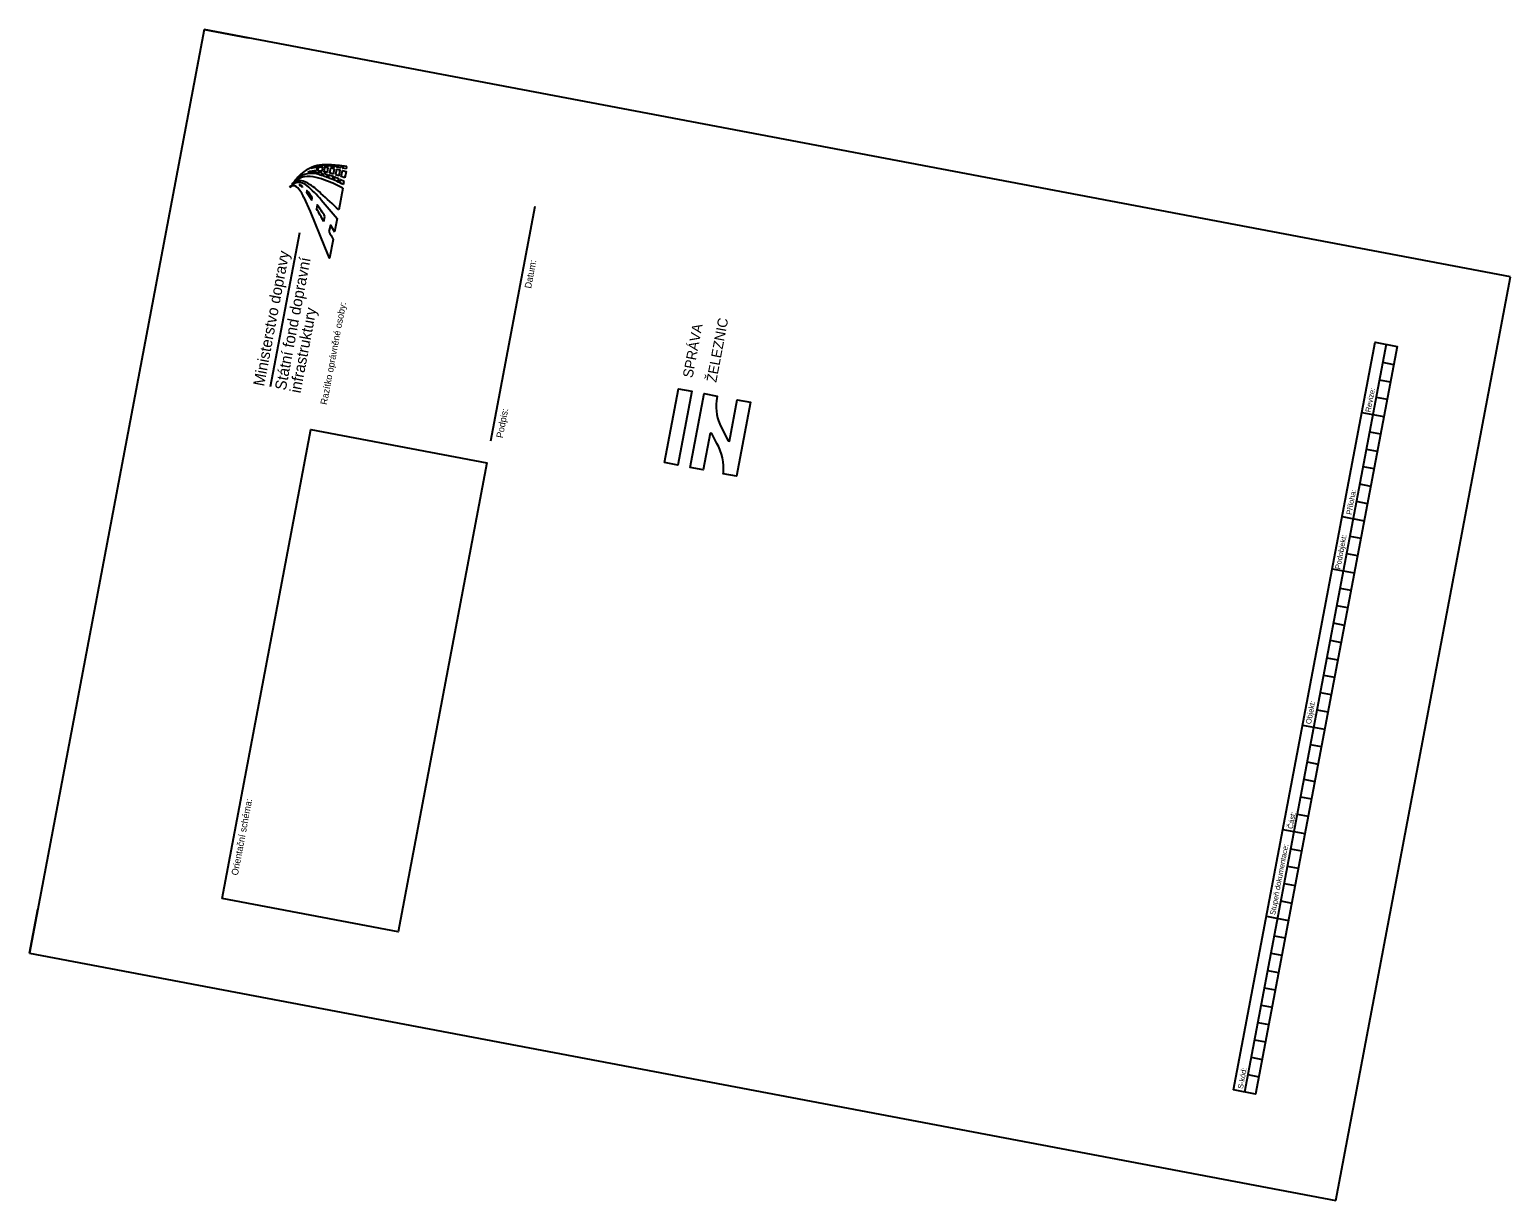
# Model space of a CAD drawing. Extents: x -526979 to -525529, y -1078878 to -1076692.
# Drawn here: x -525859.9 to -525529, y -1076953.6 to -1076692.1 of the extents above; entities that cross this region are included whole.
import ezdxf

# ---------------------------------------------------------------- set-up
doc = ezdxf.new("R2010")
doc.units = 0
for name, color, linetype in [('Default', 7, 'Continuous'), ('ramek', 7, 'Continuous'), ('Rozpiska_Logo', 7, 'Continuous'), ('Rozpiska_pola_3', 7, 'Continuous'), ('Rozpiska_pole_2', 7, 'Continuous'), ('Rozpiska_pole_8', 7, 'Continuous')]:
    doc.layers.add(name, color=color, linetype=linetype)

# ---------------------------------------------------------------- blocks, each defined once
blk = doc.blocks.new('_U77')
at = {"layer": 'Rozpiska_pole_8'}
for p, q in [((85, 0), (-85, 0)), ((-81.05, 0), (-81.05, -2.5)), ((-77.1, 0), (-77.1, -2.5)), ((-73.15, 0), (-73.15, -2.5)), ((-69.2, 0), (-69.2, -2.5)), ((-65.25, 0), (-65.25, -2.5)), ((-61.3, 0), (-61.3, -2.5)), ((-57.35, 0), (-57.35, -2.5)), ((-53.4, 0), (-53.4, -2.5)), ((-49.45, 0), (-49.45, -2.5)), ((-45.5, 2.5), (-45.5, -2.5)), ((-41.55, 0), (-41.55, -2.5)), ((-37.6, 0), (-37.6, -2.5)), ((-33.65, 0), (-33.65, -2.5)), ((-29.7, 0), (-29.7, -2.5)), ((-25.75, 2.5), (-25.75, -2.5)), ((-21.8, 0), (-21.8, -2.5)), ((-17.85, 0), (-17.85, -2.5)), ((-13.9, 0), (-13.9, -2.5)), ((-9.95, 0), (-9.95, -2.5)), ((-6, 0), (-6, -2.5)), ((-2.05, 2.5), (-2.05, -2.5)), ((1.9, 0), (1.9, -2.5)), ((5.85, 0), (5.85, -2.5)), ((9.8, 0), (9.8, -2.5)), ((13.75, 0), (13.75, -2.5)), ((17.7, 0), (17.7, -2.5)), ((21.65, 0), (21.65, -2.5)), ((25.6, 0), (25.6, -2.5)), ((29.55, 0), (29.55, -2.5)), ((33.5, 2.5), (33.5, -2.5)), ((37.45, 0), (37.45, -2.5)), ((41.4, 0), (41.4, -2.5)), ((45.35, 2.5), (45.35, -2.5)), ((49.3, 0), (49.3, -2.5)), ((53.25, 0), (53.25, -2.5)), ((57.2, 0), (57.2, -2.5)), ((61.15, 0), (61.15, -2.5)), ((65.1, 0), (65.1, -2.5)), ((69.05, 2.5), (69.05, -2.5)), ((73, 0), (73, -2.5)), ((76.95, 0), (76.95, -2.5)), ((80.9, 0), (80.9, -2.5))]:
    blk.add_line(p, q, dxfattribs=at)
blk.add_lwpolyline([(-85, 2.5), (85, 2.5), (85, -2.5), (-85, -2.5)], close=True, dxfattribs=at)
at = {"layer": 'Default'}
for s, p in [('S-kód:', (-84.45, 0.49)), ('Stupeň dokumentace:', (-44.97, 0.65)), ('Část:', (-25.34, 0.34)), ('Objekt:', (-1.57, 0.7)), ('Podobjekt:', (33.64, 0.7)), ('Příloha:', (46.07, 0.49)), ('Revize:', (69.36, 0.56))]:
    blk.add_text(s, height=1.2, dxfattribs=at).set_placement(p)
blk = doc.blocks.new('_U78')
at = {"layer": 'Rozpiska_pola_3'}
blk.add_line((-26.675, -18.2505), (26.675, -18.2505), dxfattribs=at)
for s, p in [('Razítko oprávněné osoby:', (-25.675, 19.2495)), ('Podpis:', (-25.675, -20.7505)), ('Datum:', (8.325, -20.7505))]:
    blk.add_text(s, height=1.5, dxfattribs=at).set_placement(p)
blk = doc.blocks.new('_U79')
at = {"layer": 'Rozpiska_pole_2'}
blk.add_lwpolyline([(-53.3255, 20.0005), (53.3245, 20.0005), (53.3245, -19.9995), (-53.3255, -19.9995)], close=True, dxfattribs=at)
blk.add_text('Orientační schéma:', height=1.5, dxfattribs=at).set_placement((-47.6755, 17.5005))
blk = doc.blocks.new('_U81')
at = {"layer": 'Rozpiska_Logo'}
blk.add_lwpolyline([(-8.4, 8.2), (8.4, 8.2), (8.4, 5.18), (-8.4, 5.18)], close=True, dxfattribs=at)
for points in [[(-0.03, -0.63), (-8.4, -0.63), (-8.4, 2.39), (8.4, 2.39), (8.4, -0.63), (7.29, -0.63)], [(1.71, -2.77), (-0.97, -4.86), (-0.97, -5.17), (8.4, -5.17), (8.4, -8.2), (-8.4, -8.2), (-8.4, -5.17), (-8.33, -5.17)], [(-2.03, -2.5), (-0.03, -0.99), (-0.03, -0.63)]]:
    blk.add_lwpolyline(points, dxfattribs=at)
for centre, radius, start, end in [((-9.2, 5.63), 10.84, 274.6014, 311.4254), ((8.06, -10.96), 10.35, 94.2142, 127.7808)]:
    blk.add_arc(centre, radius, start, end, dxfattribs=at)
blk = doc.blocks.new('_U80')
at = {"layer": 'Rozpiska_Logo'}
blk.add_blockref('_U81', (-11.06, -0.36), dxfattribs=at)
at = {"layer": 'Default'}
for s, p in [('SPRÁVA', (0.17, 5.18)), ('ŽELEZNIC', (0.17, -0.22))]:
    blk.add_text(s, height=2.25, dxfattribs=at).set_placement(p)
blk = doc.blocks.new('_U82')
at = {"layer": 'Rozpiska_Logo'}
for p, q in [((-25.55, 1.47), (9.42, 1.47)), ((17.01, 0.17), (17.67, 0.17)), ((19.44, 2.74), (19.65, 2.74)), ((24.47, 0.37), (23.67, 0.33)), ((24.55, 0.1), (23.74, 0.04)), ((24.87, -2.59), (23.75, -2.61)), ((23.78, -2.15), (24.82, -2.11)), ((24.77, -1.23), (23.79, -1.27)), ((23.82, -0.91), (24.73, -0.86)), ((12.89, -3.34), (14.03, -3.39)), ((20.96, -6.16), (16.08, -6.16)), ((21.8, -6.16), (22.58, -6.16)), ((23.3, -6.16), (23.76, -6.16)), ((23.71, -3.52), (24.87, -3.52)), ((25.35, -6.16), (25.9, -6.16))]:
    blk.add_line(p, q, dxfattribs=at)
for points in [[(19.96, 3.49), (19.96, 3.49), (19.79, 3.49)], [(9.34, -6.16), (5.04, -6.16), (7.34, -4.64), (14.55, -0.05), (17.35, 1.99)], [(18.95, 1.62), (18.95, 1.62), (18.5, 1.63)], [(23.44, 0.31), (23.12, 0.29), (23.11, -0.01), (23.44, 0.02)], [(24.74, 0.12), (24.87, 0.13), (24.77, 0.39), (24.62, 0.38)], [(17.52, -1.91), (14.11, -6.16), (11.04, -6.16)], [(16.26, -1.24), (16.26, -1.24), (15.34, -1.24)], [(23.36, -2.17), (22.86, -2.19), (22.8, -2.62), (23.31, -2.62), (23.19, -3.52), (22.64, -3.52), (22.53, -3.93), (23.11, -3.94), (22.93, -4.8), (22.28, -4.79), (22.21, -5.26), (22.78, -5.28), (22.58, -6.16)], [(23.44, -0.93), (23.04, -0.95), (22.99, -1.3), (23.42, -1.28)], [(25.03, -1.21), (25.21, -1.21), (25.13, -0.83), (24.96, -0.84)], [(25.21, -2.59), (25.46, -2.58), (25.39, -2.09), (25.14, -2.1)], [(12.37, -4.94), (12.37, -4.94), (10.91, -4.9)], [(23.68, -3.98), (23.57, -4.82), (24.83, -4.85), (24.85, -4), (23.68, -3.98)], [(25.3, -3.97), (25.62, -3.97), (25.57, -3.52), (25.27, -3.52)], [(25.35, -6.16), (25.34, -5.35), (25.73, -5.36), (25.69, -4.87), (25.33, -4.86)]]:
    blk.add_lwpolyline(points, dxfattribs=at)
blk.add_lwpolyline([(23.3, -6.16), (23.47, -5.32), (24.81, -5.33), (24.78, -6.16)], close=True, dxfattribs=at)
for centre, radius, start, end in [((12.76, 8.51), 7.97, 305.1305, 325.9532), ((18.32, 4.56), 1.16, 333.7821, 60.3253), ((17.67, 2.96), 2.89, 35.1291, 64.7751), ((18.25, 3.75), 1.56, 319.6022, 350.325), ((18.31, 3.72), 1.66, 323.7342, 351.8118), ((16.62, 0), 6.05, 44.354, 59.6129), ((17.93, 2.79), 2.99, 8.8325, 54.3171), ((18.21, 3.34), 2.23, 358.3059, 35.1291), ((-78.21, -122.9), 161.35, 51.8348, 52.3632), ((15.77, -4.24), 10.18, 55.8173, 63.4675), ((17.76, 1.15), 4.43, 21.6804, 44.0388), ((17.11, -3.06), 8.47, 45.7577, 58.8317), ((18.55, 0.69), 4.4, 29.5083, 48.0349), ((0.31, 18.76), 24.99, 311.9225, 316.7053), ((-3.05, 14.6), 26.37, 321.2414, 331.1155), ((-17.55, 32.68), 47.93, 317.2846, 319.5966), ((5.62, 7.28), 15.98, 326.3997, 339.6645), ((17.32, 3.37), 3.12, 331.1155, 358.3059), ((16.3, 3.32), 4.59, 339.6691, 359.0927), ((16.31, 0.66), 5.96, 354.8309, 20.9259), ((5.52, 1.21), 16.76, 348.0644, 356.2998), ((18.63, 0.68), 4.33, 12.5999, 30.087), ((18.31, 0.44), 4.7, 350.7277, 14.6627), ((19.3, -0.21), 4.41, 6.9884, 33.3949), ((17.74, -0.08), 5.72, 3.8889, 23.6112), ((17.15, -3.14), 8.5, 32.4145, 46.3283), ((11.81, -0.49), 11.64, 357.822, 2.4688), ((14.25, -1.23), 9.57, 1.9262, 7.6145), ((19.52, -1.39), 5.39, 19.1508, 35.05), ((12.94, -3.42), 12.13, 18.2045, 25.0006), ((19.04, -2.12), 6.36, 13.4543, 33.7828), ((16.65, -1.88), 8.15, 7.2316, 14.102), ((18.93, -1.73), 6.1, 8.3249, 17.6578), ((-37.59, 58.14), 79.55, 309.3914, 311.7102), ((-24.24, 38.57), 56.8, 312.3671, 315.4937), ((-382.7, 244.69), 471.11, 327.8282, 328.4861), ((-6.13, 2.58), 28.46, 342.1151, 350.2059), ((-9.65, 3.13), 32.79, 343.5415, 349.3721), ((2.61, 1.28), 20.4, 348.131, 355.4957), ((42.05, -2.94), 18.71, 174.904, 177.6286), ((18.34, -2.86), 5.41, 352.9784, 2.6252), ((-28.49, -1.16), 52.28, 358.9091, 359.8809), ((5.4, -2.79), 19.43, 1.988, 4.6084), ((18.56, -3.02), 6.33, 355.4573, 3.8566), ((21.25, -2.11), 3.88, 0.0904, 13.2769), ((14.56, -3.78), 10.71, 1.3852, 6.3824), ((9.49, -4.69), 16.25, 2.7985, 14.4251), ((31.1, -31.53), 33.42, 127.1682, 130.6153), ((29.54, -25.09), 26.47, 130.4231, 134.3309), ((-14.08, -5.68), 39.42, 1.1818, 2.4809), ((-7.07, -7.73), 33.01, 2.7322, 6.6695)]:
    blk.add_arc(centre, radius, start, end, dxfattribs=at)
for s, p in [('Ministerstvo dopravy', (-25.9, 2.9)), ('Státní fond dopravní', (-25.9, -2.03)), ('infrastruktury', (-25.9, -5.4))]:
    blk.add_text(s, height=2.5, rotation=0.0062, dxfattribs=at).set_placement(p)
blk = doc.blocks.new('_U76')
at = {"layer": 'Default'}
for p, q in [((-2100, 0), (-2100, 2970)), ((-2100, 2970), (0, 2970)), ((-2100, 2970), (-2000, 2970)), ((-2100, 2970), (-2100, 2870)), ((0, 2970), (-100, 2970)), ((0, 2970), (0, 0)), ((-2100, 0), (-2100, 100)), ((0, 0), (-2100, 0))]:
    blk.add_line(p, q, dxfattribs=at)

msp = doc.modelspace()

# ---------------------------------------------------------------- block references
at = {"layer": 'ramek', "xscale": 0.10000000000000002, "yscale": -0.10000000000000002, "rotation": -100.71062087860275}
msp.add_blockref('_U76', (-525568.03, -1076953.61), dxfattribs=at)
at = {"layer": 'Rozpiska_Logo', "rotation": 79.28937912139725}
for name, p in [('_U82', (-525799.82, -1076746.96)), ('_U80', (-525706.69, -1076771.13))]:
    msp.add_blockref(name, p, dxfattribs=at)
at = {"layer": 'Rozpiska_pola_3', "rotation": 79.28937912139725}
msp.add_blockref('_U78', (-525769.76, -1076754.32), dxfattribs=at)
at = {"layer": 'Rozpiska_pole_2', "rotation": 79.28937912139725}
msp.add_blockref('_U79', (-525787.28, -1076837.52), dxfattribs=at)
at = {"layer": 'Rozpiska_pole_8', "rotation": 79.28937912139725}
msp.add_blockref('_U77', (-525572.59, -1076845.89), dxfattribs=at)

doc.saveas('drawing.dxf')
